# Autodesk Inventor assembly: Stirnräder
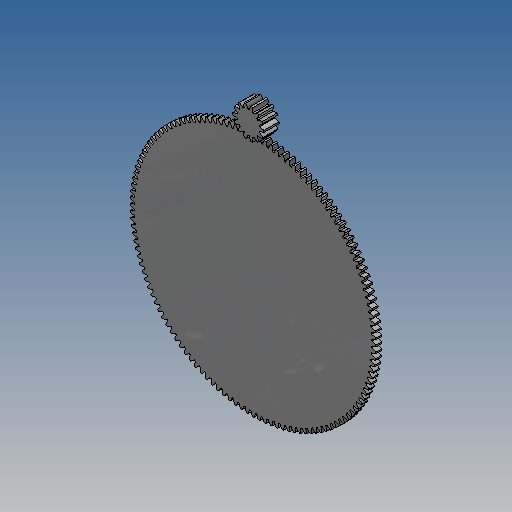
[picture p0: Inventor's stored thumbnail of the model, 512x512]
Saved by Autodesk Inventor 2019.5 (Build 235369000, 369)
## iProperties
Created: 2021-12
Part Number: Stirnräder
Document SubType Name: Assembly
Categories: <?xml version="1.0" encoding="UTF-16"?> <MemberInstance><Categories><FamilyTemplate/><ParamToTemplateMap><ParamToTemplate><ParamToTemplate CategoryParameter="//
Mass: 38.8156 g
Surface Area: 72.4414 cm^2
Volume: 4.94467 cm^3
Density: 7.85 g/cm^3
ClientObjectVersion: 1
Mass: 0.04
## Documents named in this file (3)
- C:\Users\Walter\Downloads\Zahn\Baugruppe1\Konstruktions-Assistent\Stirnräder1.iam
- C:\Users\Walter\Downloads\Zahn\Baugruppe1\Konstruktions-Assistent\Stirnzahnrad11.ipt
- C:\Users\Walter\Downloads\Zahn\Baugruppe1\Konstruktions-Assistent\Stirnzahnrad21.ipt
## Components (2 placed, 2 different names)
1. Stirnzahnrad1:1 — Drehung:1
2. Stirnzahnrad2:1 — Drehung:1
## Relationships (1: RelateRotation 1)
- Drehung:1 [RelateRotation]: Stirnzahnrad1:1 ↔ Stirnzahnrad2:1
